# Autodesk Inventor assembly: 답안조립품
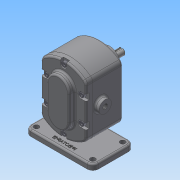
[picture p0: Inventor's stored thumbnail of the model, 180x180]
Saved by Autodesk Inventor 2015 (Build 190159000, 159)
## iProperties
Created: 2019-03
Part Number: 답안조립품
Document SubType Name: Assembly
Designer: user
Author: user
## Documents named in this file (10)
- C:\Users\user\Desktop\490307V1007\답안조립품.iam
- C:\Users\user\Desktop\490307V1007\본체.ipt
- C:\Users\user\Desktop\490307V1007\커버.ipt
- C:\Users\user\Desktop\490307V1007\베어링부시.ipt
- C:\Users\user\Desktop\490307V1007\오일 실 16 28 7.ipt
- C:\Users\user\Desktop\490307V1007\메인축.ipt
- C:\Users\user\Desktop\490307V1007\서브축.ipt
- C:\Users\user\Desktop\490307V1007\볼트 M5.ipt
- C:\Users\user\Desktop\490307V1007\키 6 x 6 x 18.ipt
- C:\Users\user\Desktop\490307V1007\스퍼기어.ipt
